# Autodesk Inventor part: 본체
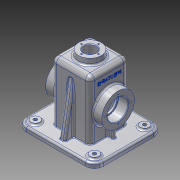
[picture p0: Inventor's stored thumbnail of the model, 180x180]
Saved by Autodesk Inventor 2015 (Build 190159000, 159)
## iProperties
Created: 2016-02
Part Number: 본체
Material: 알루미늄 6061
Document SubType Name: Modeling
Designer: Administrator
Density: 2.7 g/cm^3
Appearance: 알루미늄 - 평지
Mass: 804.638 g
Surface Area: 910.774 cm^2
Volume: 298.014 cm^3
Author: Administrator
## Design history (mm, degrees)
sketch "스케치1"
  geometry: L1 (-65, 57.5)-(65, 57.5); L2 (65, 57.5)-(65, -57.5); L3 (65, -57.5)-(-65, -57.5); L4 (-65, -57.5)-(-65, 57.5); L5 (-65, 57.5)-(65, -57.5); L6 (65, 57.5)-(-65, -57.5); 1 further point
  constraints: 12 end point, 2 midpoint, 2 parallel, 1 horizontal, 1 perpendicular
  dimensions: "d0" = 115 distance of L1.end L2.end; "d1" = 130 distance of L1.start L1.end
extrude "돌출1" new body sketch "스케치1" distance "d2" = 8; taper "d3" = 0 deg
sketch "스케치2"
  geometry: L1 (-32.5, 32.5)-(32.5, 32.5); L2 (32.5, 32.5)-(32.5, -32.5); L3 (32.5, -32.5)-(-32.5, -32.5); L4 (-32.5, -32.5)-(-32.5, 32.5); L5 (-32.5, 32.5)-(32.5, -32.5); L6 (32.5, 32.5)-(-32.5, -32.5); 1 further point
  constraints: 12 end point, 2 midpoint, 2 parallel, 1 horizontal, 1 perpendicular
  dimensions: "d4" = 65 distance of L1.start L1.end; "d5" = 65 distance of L1.end L2.end
extrude "돌출2" join sketch "스케치2" distance "d6" = 100; taper "d7" = 0 deg
sketch "스케치3"
  geometry: L1 (65, 57.5)-(-65, 57.5) reference; L2 (-5, -47.5)-(5, -47.5); L3 (5, -47.5)-(5, 47.5); L4 (5, 47.5)-(-5, 47.5); L5 (-5, 47.5)-(-5, -47.5); L6 (-5, -47.5)-(5, 47.5); L7 (5, -47.5)-(-5, 47.5); 1 further point
  constraints: 12 end point, 2 midpoint, 2 parallel, 1 horizontal, 1 perpendicular
  dimensions: "d8" = 10 distance of L3.end L4.end; "d9" = 10 distance between parallel lines of L1 L4
extrude "돌출3" join sketch "스케치3" distance "d10" = 100; taper "d11" = 0 deg
feature "면 기울기1" dims angle "d12" = 10 deg
sketch "스케치4"
  geometry: L1 (42.5, -3)-(-42.5, -3); L2 (-42.5, -3)-(-42.5, 3); L3 (-42.5, 3)-(42.5, 3); L4 (42.5, 3)-(42.5, -3); L5 (42.5, -3)-(-42.5, 3); L6 (-42.5, -3)-(42.5, 3); 1 further point
  constraints: 12 end point, 2 midpoint, 2 parallel, 1 horizontal, 1 perpendicular
  dimensions: "d13" = 6 distance of L3.end L1.start; "d14" = 85 distance of L1.start L1.end
extrude "돌출4" join sketch "스케치4" distance "d15" = 55; taper "d16" = 0 deg
sketch "스케치5"
  geometry: C1 r 20 at (0, 0); 1 further point
  constraints: 1 centre point, 1 coincident
  dimensions: "d17" = 40 diameter of C1
extrude "돌출5" join sketch "스케치5" distance "d18" = 10; taper "d19" = 0 deg
sketch "스케치7"
  geometry: L1 (65, 57.5)-(-65, 57.5) reference; L2 (-65, 57.5)-(-65, -57.5) reference; L3 (-65, -57.5)-(65, -57.5) reference; L4 (65, -57.5)-(65, 57.5) reference; L5 (60, -52.5)-(-60, -52.5); L6 (-60, -52.5)-(-60, 52.5); L7 (-60, 52.5)-(60, 52.5); L8 (60, 52.5)-(60, -52.5); 1 further point
  constraints: 8 end point, 3 other
  dimensions: "d21" = 5 distance between parallel lines of L3 L5
extrude "돌출6" join sketch "스케치7" distance "d22" = 2; taper "d23" = 0 deg
sketch "스케치9"
  geometry: L1 (-65, -57.5)-(65, -57.5) reference; L2 (65, -57.5)-(65, 57.5) reference; C1 r 7.5 at (50, -42.5); 1 further point
  constraints: 1 centre point
  dimensions: "d36" = 15 diameter of C1; "d37" = 15 distance from line of L1 C1.centre; "d38" = 15 distance from line of L2 C1.centre
extrude "돌출8" join sketch "스케치9" distance "d39" = 3; taper "d40" = 0 deg
hole "구멍1" diameter "d49" = 6; stored, may be unused: countersink angle "d53" = 90 deg, drill point angle "d55" = 118 deg; dims "d47" = 10, "d48" = 10, "d50" = 6, "d51" = 4, "d52" = 2, "d54" = 8
hole "구멍2" diameter "d58" = 6; stored, may be unused: countersink angle "d62" = 90 deg, drill point angle "d64" = 118 deg; dims "d56" = 10, "d57" = 10, "d59" = 6, "d60" = 4, "d61" = 2, "d63" = 8
hole "구멍3" diameter "d67" = 6; stored, may be unused: countersink angle "d71" = 90 deg, drill point angle "d73" = 118 deg; dims "d65" = 10, "d66" = 10, "d68" = 6, "d69" = 4, "d70" = 2, "d72" = 8
hole "구멍4" diameter "d76" = 6; stored, may be unused: countersink angle "d80" = 90 deg, drill point angle "d82" = 118 deg; dims "d74" = 10, "d75" = 10, "d77" = 6, "d78" = 4, "d79" = 2, "d81" = 8
sketch "스케치13"
  geometry: L1 (47.5, 8)-(57.5, 8) reference; L2 (57.5, 8)-(57.5, 0) reference; L3 (57.5, 0)-(52.5, 0) reference; L4 (52.5, 0)-(52.5, -2) reference; L5 (52.5, -2)-(-52.5, -2) reference; L6 (-52.5, -2)-(-52.5, 0) reference; L7 (-52.5, 0)-(-57.5, 0) reference; L8 (-57.5, 0)-(-57.5, 8) reference; L9 (-57.5, 8)-(-47.5, 8) reference; L10 (-47.5, 8)-(-32.5, 93.069) reference; L11 (-32.5, 93.069)-(-32.5, 108) reference; L12 (-32.5, 108)-(-20, 108) reference; L13 (-20, 108)-(-20, 118) reference; L14 (-20, 118)-(20, 118) reference; L15 (20, 118)-(20, 108) reference; L16 (20, 108)-(32.5, 108) reference; L17 (32.5, 108)-(32.5, 93.069) reference; L18 (32.5, 93.069)-(47.5, 8) reference; C1 r 27.5 at (0, 53); 1 further point
  constraints: 1 centre point, 1 vertical alignment
  dimensions: "d104" = 55 diameter of C1
extrude "돌출12" join sketch "스케치13" stored distance "d105" = 95; taper "d106" = 0 deg
sketch "스케치14"
  geometry: L1 (-52.379, 53)-(-27.5, 53); L2 (-27.5, 53)-(-27.5, 68); L3 (-27.5, 68)-(-30.5, 68); L4 (-30.5, 68)-(-30.5, 70.5); L5 (-30.5, 70.5)-(-52.379, 70.5); L6 (-52.379, 70.5)-(-52.379, 53); L7 (-60, -2)-(60, -2) reference; L8 (-32.5, 8)-(-32.5, 108) reference; 1 further point
  constraints: 12 end point, 5 perpendicular, 1 horizontal
  dimensions: "d107" = 55 distance between parallel lines of L7 L1; "d108" = 5 distance between parallel lines of L2 L8; "d109" = 3 distance of L2.end L3.end; "d111" = 30 diameter of L3 L1; "d112" = 35 diameter of L5 L1; "d113" = 19.87908 distance between parallel lines of L8 L6
revolve "회전2" sketch "스케치14" stored, may be unused: angle "d114" = 90 deg
sketch "스케치15"
  geometry: L1 (-27.5, 27.5)-(27.5, 27.5); L2 (27.5, 27.5)-(27.5, -27.5); L3 (27.5, -27.5)-(-27.5, -27.5); L4 (-27.5, -27.5)-(-27.5, 27.5); L5 (-27.5, 27.5)-(27.5, -27.5); L6 (27.5, 27.5)-(-27.5, -27.5); 1 further point
  constraints: 12 end point, 2 midpoint, 2 parallel, 1 horizontal, 1 perpendicular
  dimensions: "d115" = 55 distance of L1.end L2.end; "d116" = 55 distance of L1.start L1.end
extrude "돌출13" cut sketch "스케치15" distance "d117" = 105; taper "d118" = 0 deg
hole "구멍6" diameter "d121" = 21; stored, may be unused: countersink angle "d125" = 90 deg, drill point angle "d127" = 118 deg; dims "d119" = 10, "d120" = 10, "d122" = 6, "d123" = 4, "d124" = 2, "d126" = 8
sketch "스케치16"
  geometry: C1 r 17.5 at (0, 0) reference; 2 further points
  constraints: 1 horizontal alignment
  dimensions: "d128" = 21 distance of C1.centre point (-21, 0)
hole "구멍7" sketch "스케치16" at (-21, 0) diameter "d129" = 3.242; stored, may be unused: countersink angle "d133" = 90 deg, drill point angle "d135" = 118 deg; dims "d130" = 8, "d131" = 4, "d132" = 2, "d134" = 10
sketch "스케치17"
  geometry: C1 r 10.5 at (0, 0) reference; 1 further point
  constraints: 1 vertical alignment
  dimensions: "d139" = 14.5 distance of C1.centre point (0, -14.5)
hole "구멍8" sketch "스케치17" at (0, -14.5) diameter "d140" = 2.459; stored, may be unused: countersink angle "d144" = 90 deg, drill point angle "d146" = 118 deg; dims "d141" = 7, "d142" = 4, "d143" = 2, "d145" = 9
fillet "모깎기1" dims "d150" = 15
fillet "모깎기2" dims "d151" = 8
fillet "모깎기3" dims "d152" = 8
fillet "모깎기4" dims "d153" = 3
fillet "모깎기10" dims "d159" = 3
fillet "모깎기11" dims "d160" = 3
fillet "모깎기12" dims "d161" = 3
fillet "모깎기13" dims "d162" = 3
fillet "모깎기14" dims "d163" = 3
fillet "모깎기15" dims "d164" = 3
fillet "모깎기16" dims "d165" = 3
fillet "모깎기17" dims "d166" = 0.3
chamfer "모따기1" distance "d167" = 1; stored, may be unused: second distance "d168" = 2, angle "d169" = 45 deg
fillet "모깎기18" dims "d170" = 10
fillet "모깎기19" dims "d171" = 3
fillet "모깎기20" dims "d172" = 3
chamfer "모따기2" distance "d174" = 1; stored, may be unused: second distance "d175" = 2, angle "d176" = 45 deg
node "작업 평면2"
sketch "스케치19"
  geometry: L1 (20, 118)-(-20, 118) reference; 2 further points
  constraints: 1 vertical alignment, 1 other
  dimensions: "d179" = 26 distance from line of L1 point (0, 92)
feature "엠보싱1" sketch "스케치19" dims "d180" = 0.5, "d181" = 0
fillet "모깎기22" dims "d182" = 1
fillet "모깎기23" dims "d183" = 3
feature "면 기울기2" dims angle "d184" = 5 deg
fillet "모깎기24" dims "d185" = 3
node "솔리드1"
pattern_linear "직사각형 패턴1" dims "d43" = 100, "d46" = 85
mirror "대칭2"
pattern_circular "원형 패턴1" dims angle "d137" = 360 deg
mirror "대칭3"
pattern_circular "원형 패턴2" dims angle "d148" = 360 deg
node "절단 모서리 투영3"
other parameters: "d178" = 82.5
